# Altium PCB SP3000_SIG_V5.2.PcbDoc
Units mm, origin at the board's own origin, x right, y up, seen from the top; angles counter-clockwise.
Board outline 86.1 x 69.65 mm, 4 copper layers (TopLayer, MidLayer1, GND, BottomLayer); 79 components, 52 nets, 252 pads, 100 vias.
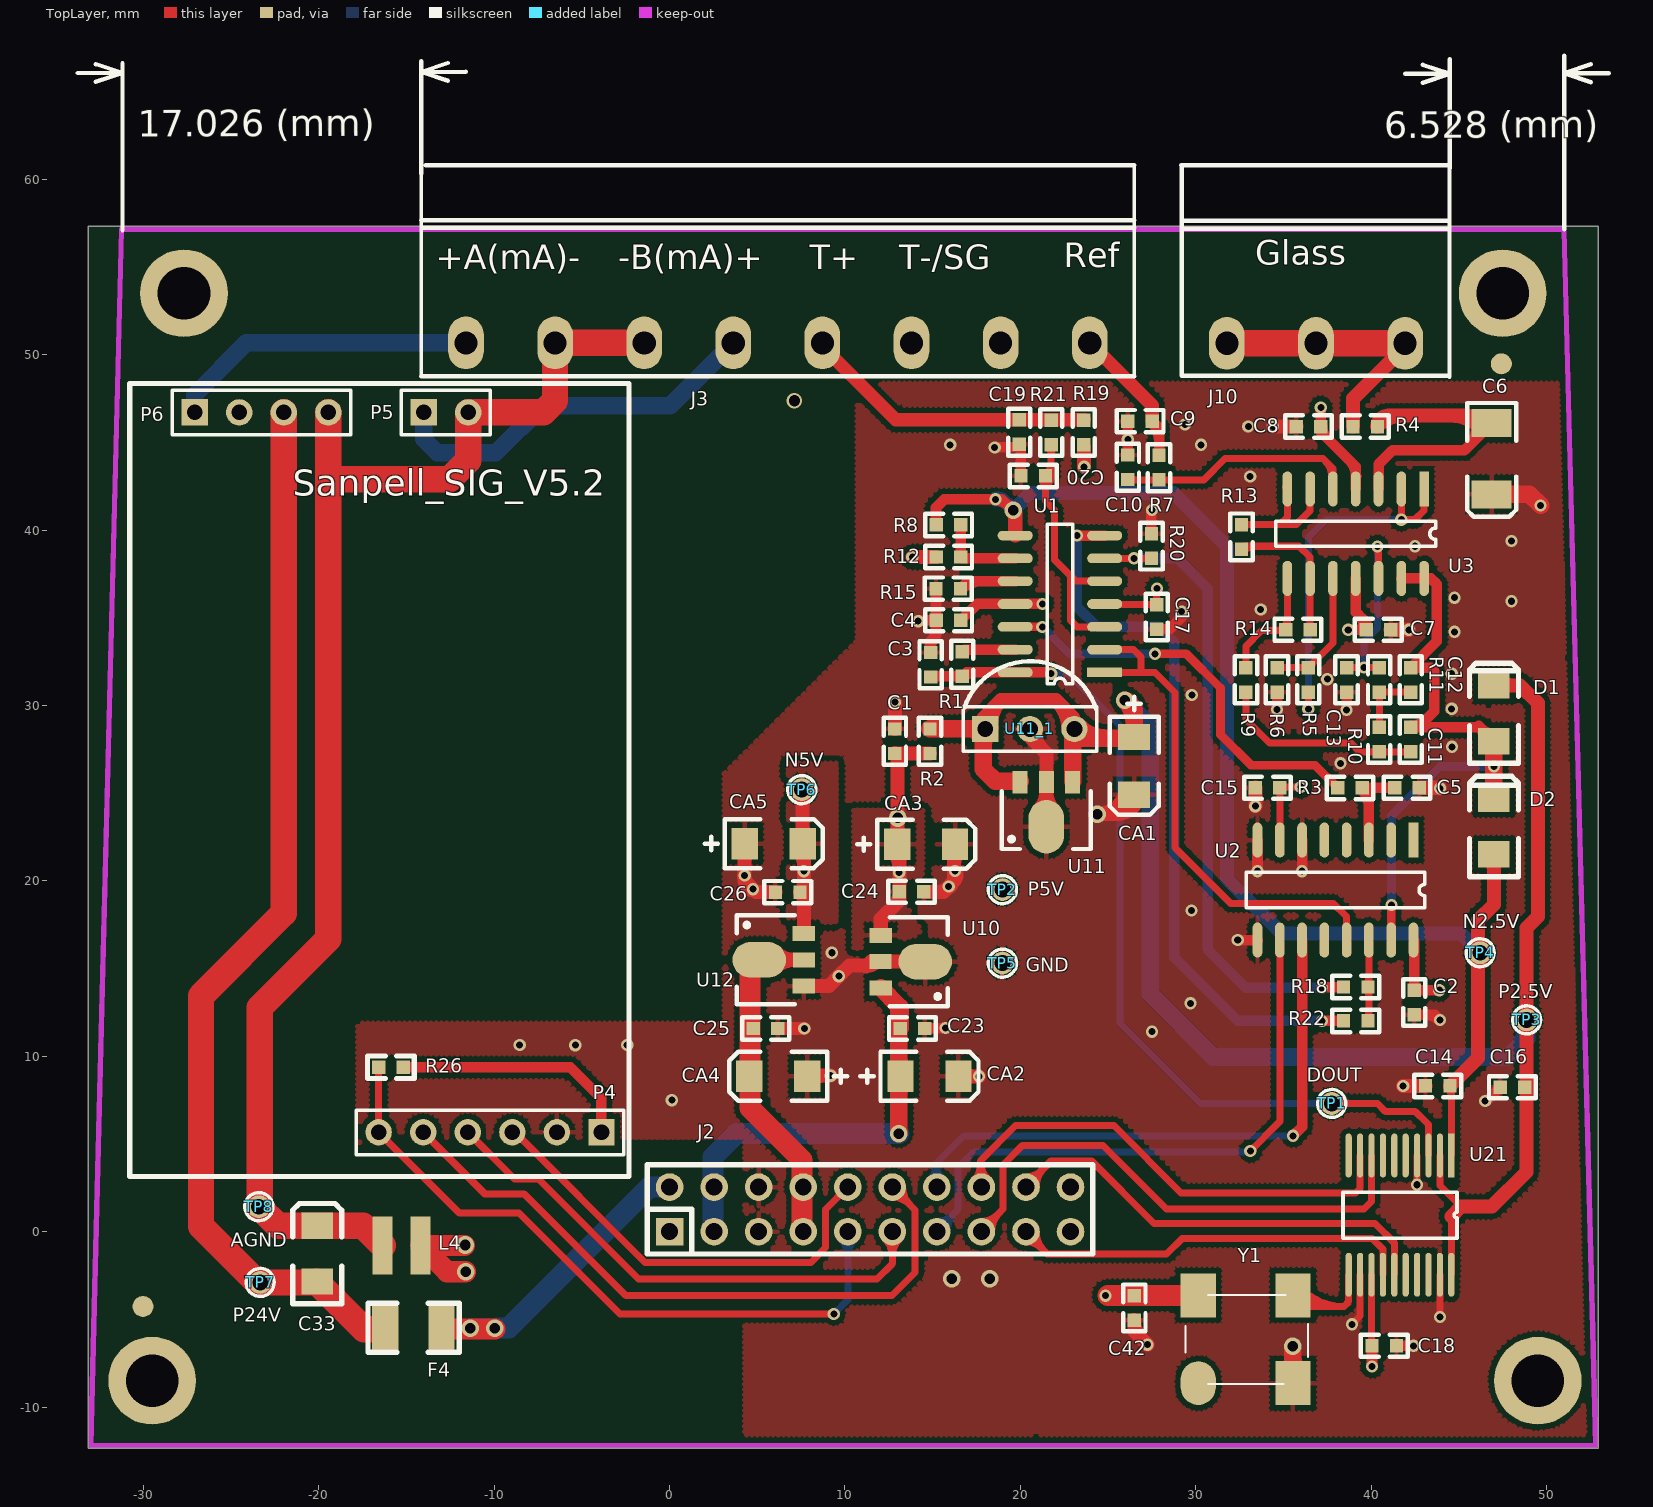
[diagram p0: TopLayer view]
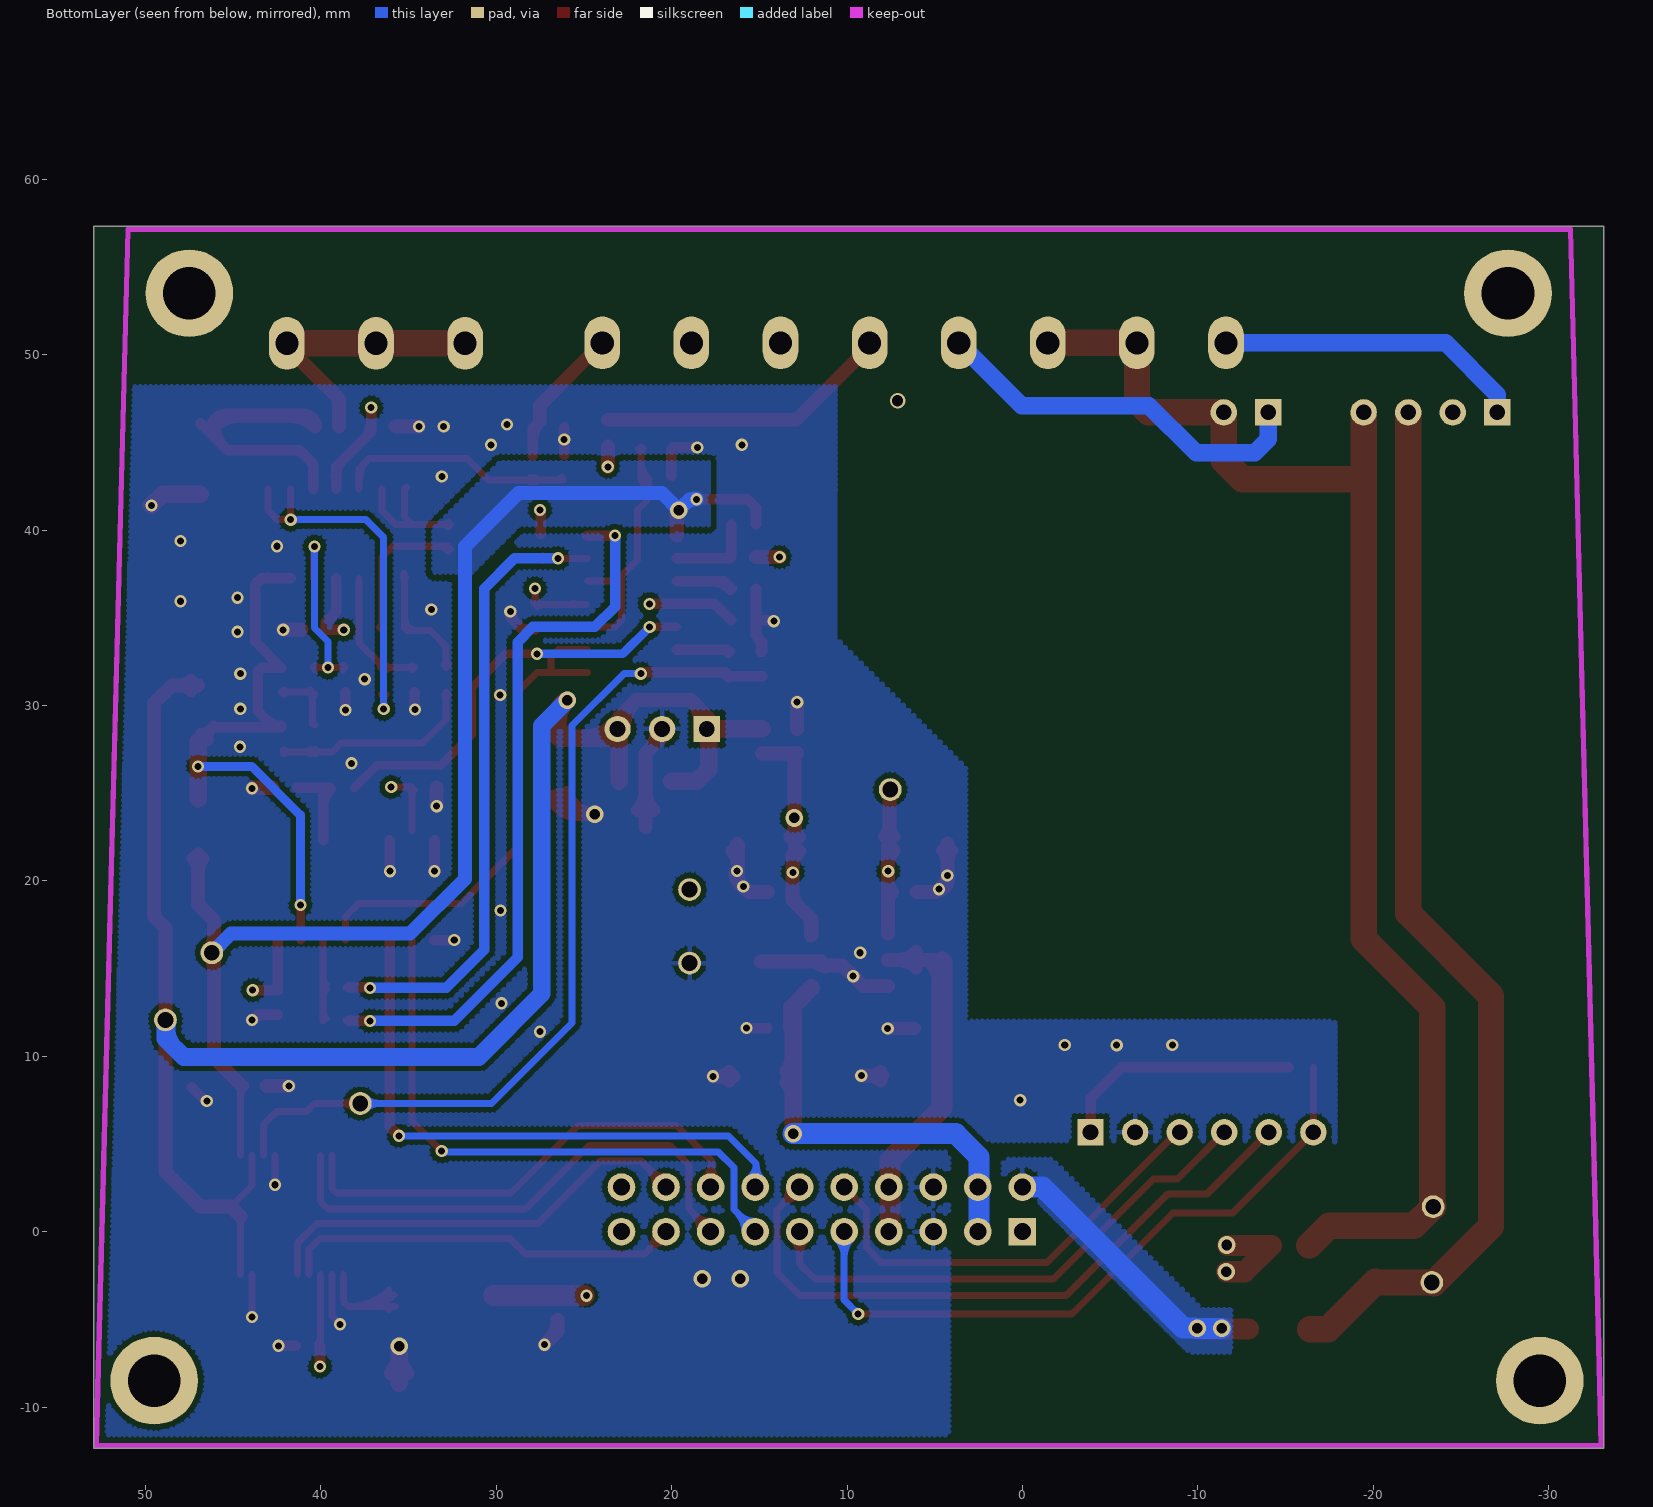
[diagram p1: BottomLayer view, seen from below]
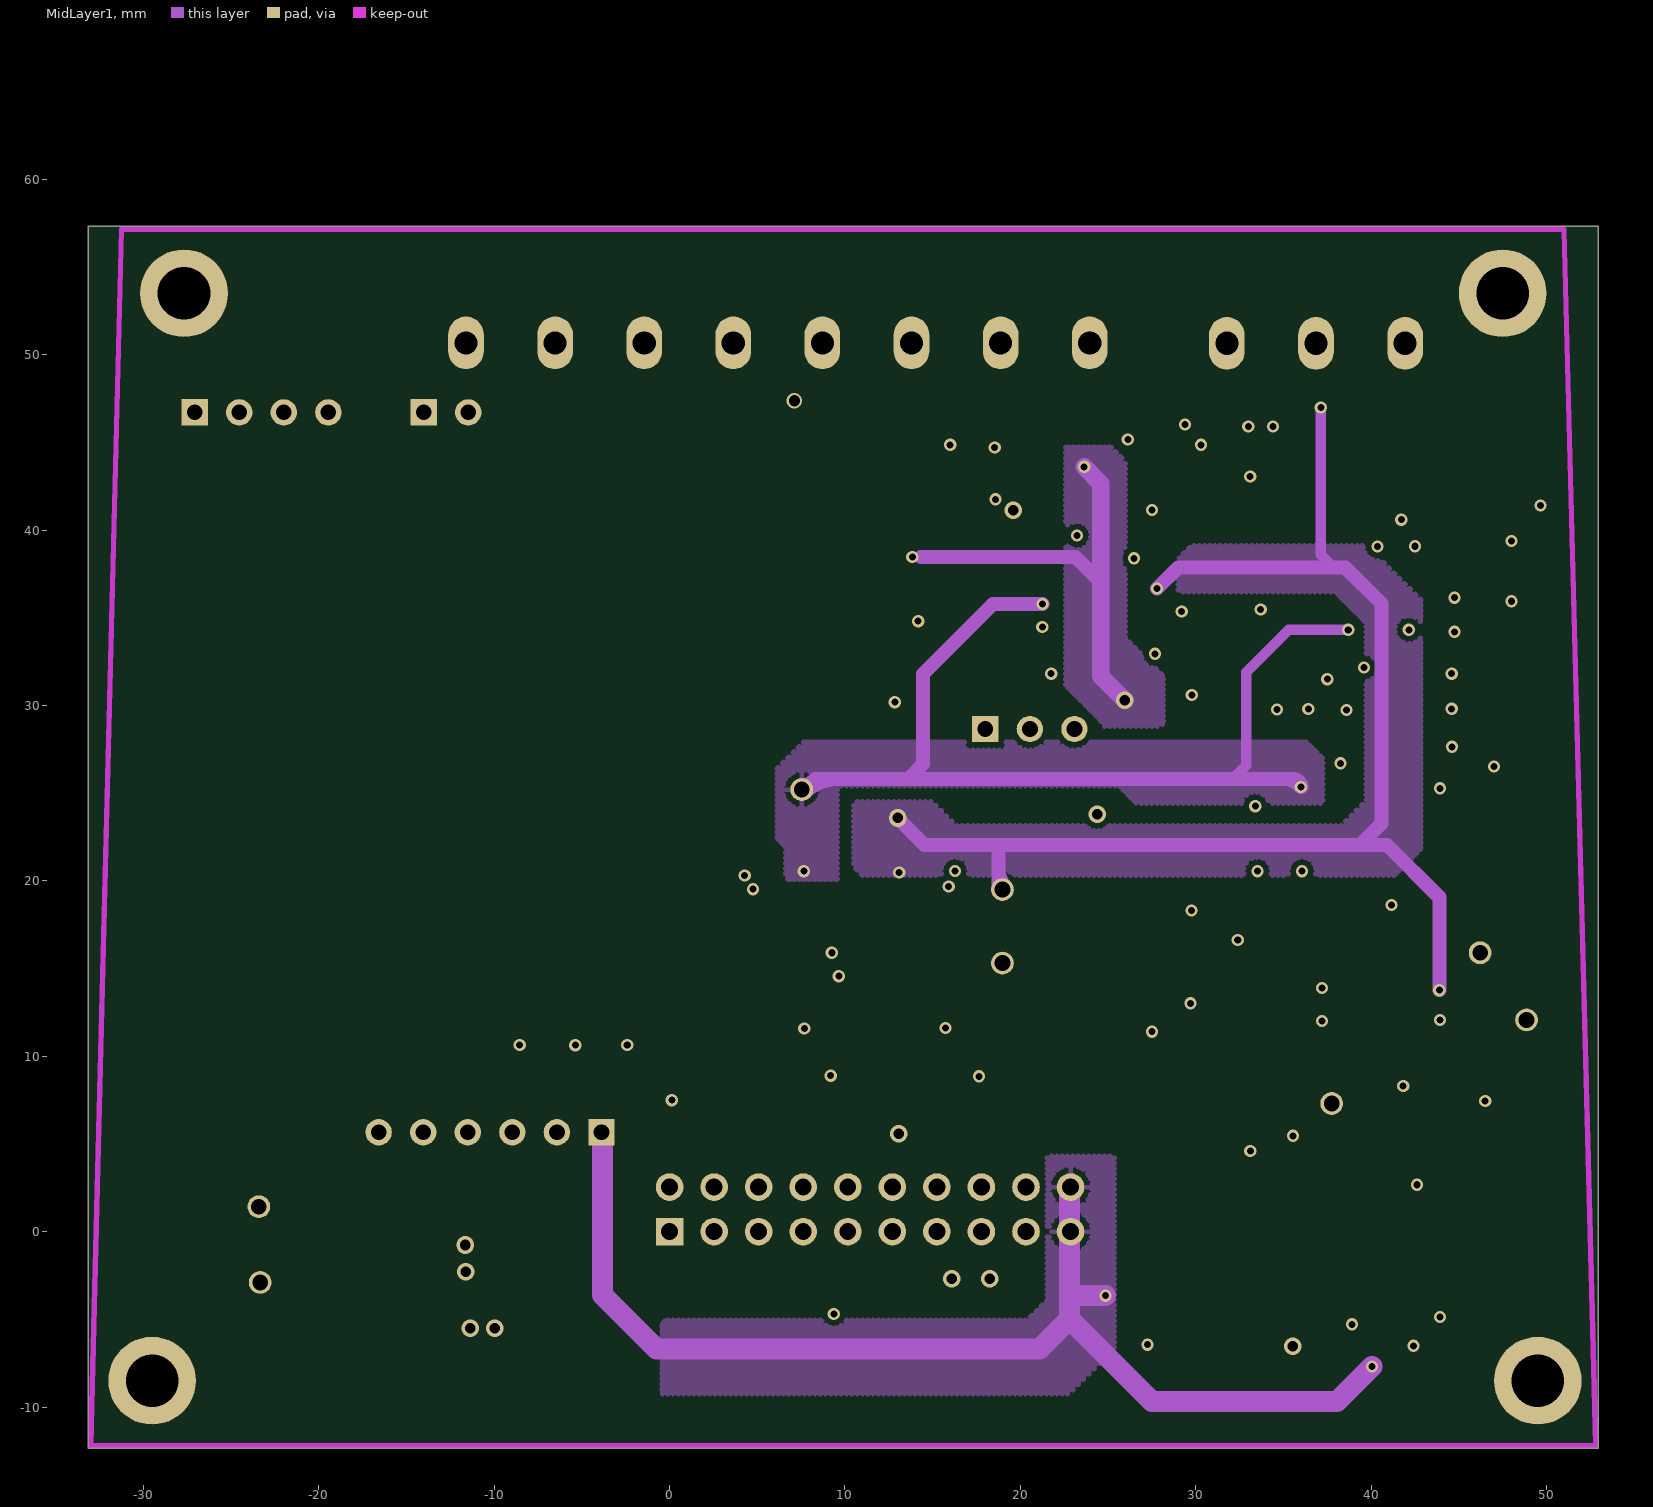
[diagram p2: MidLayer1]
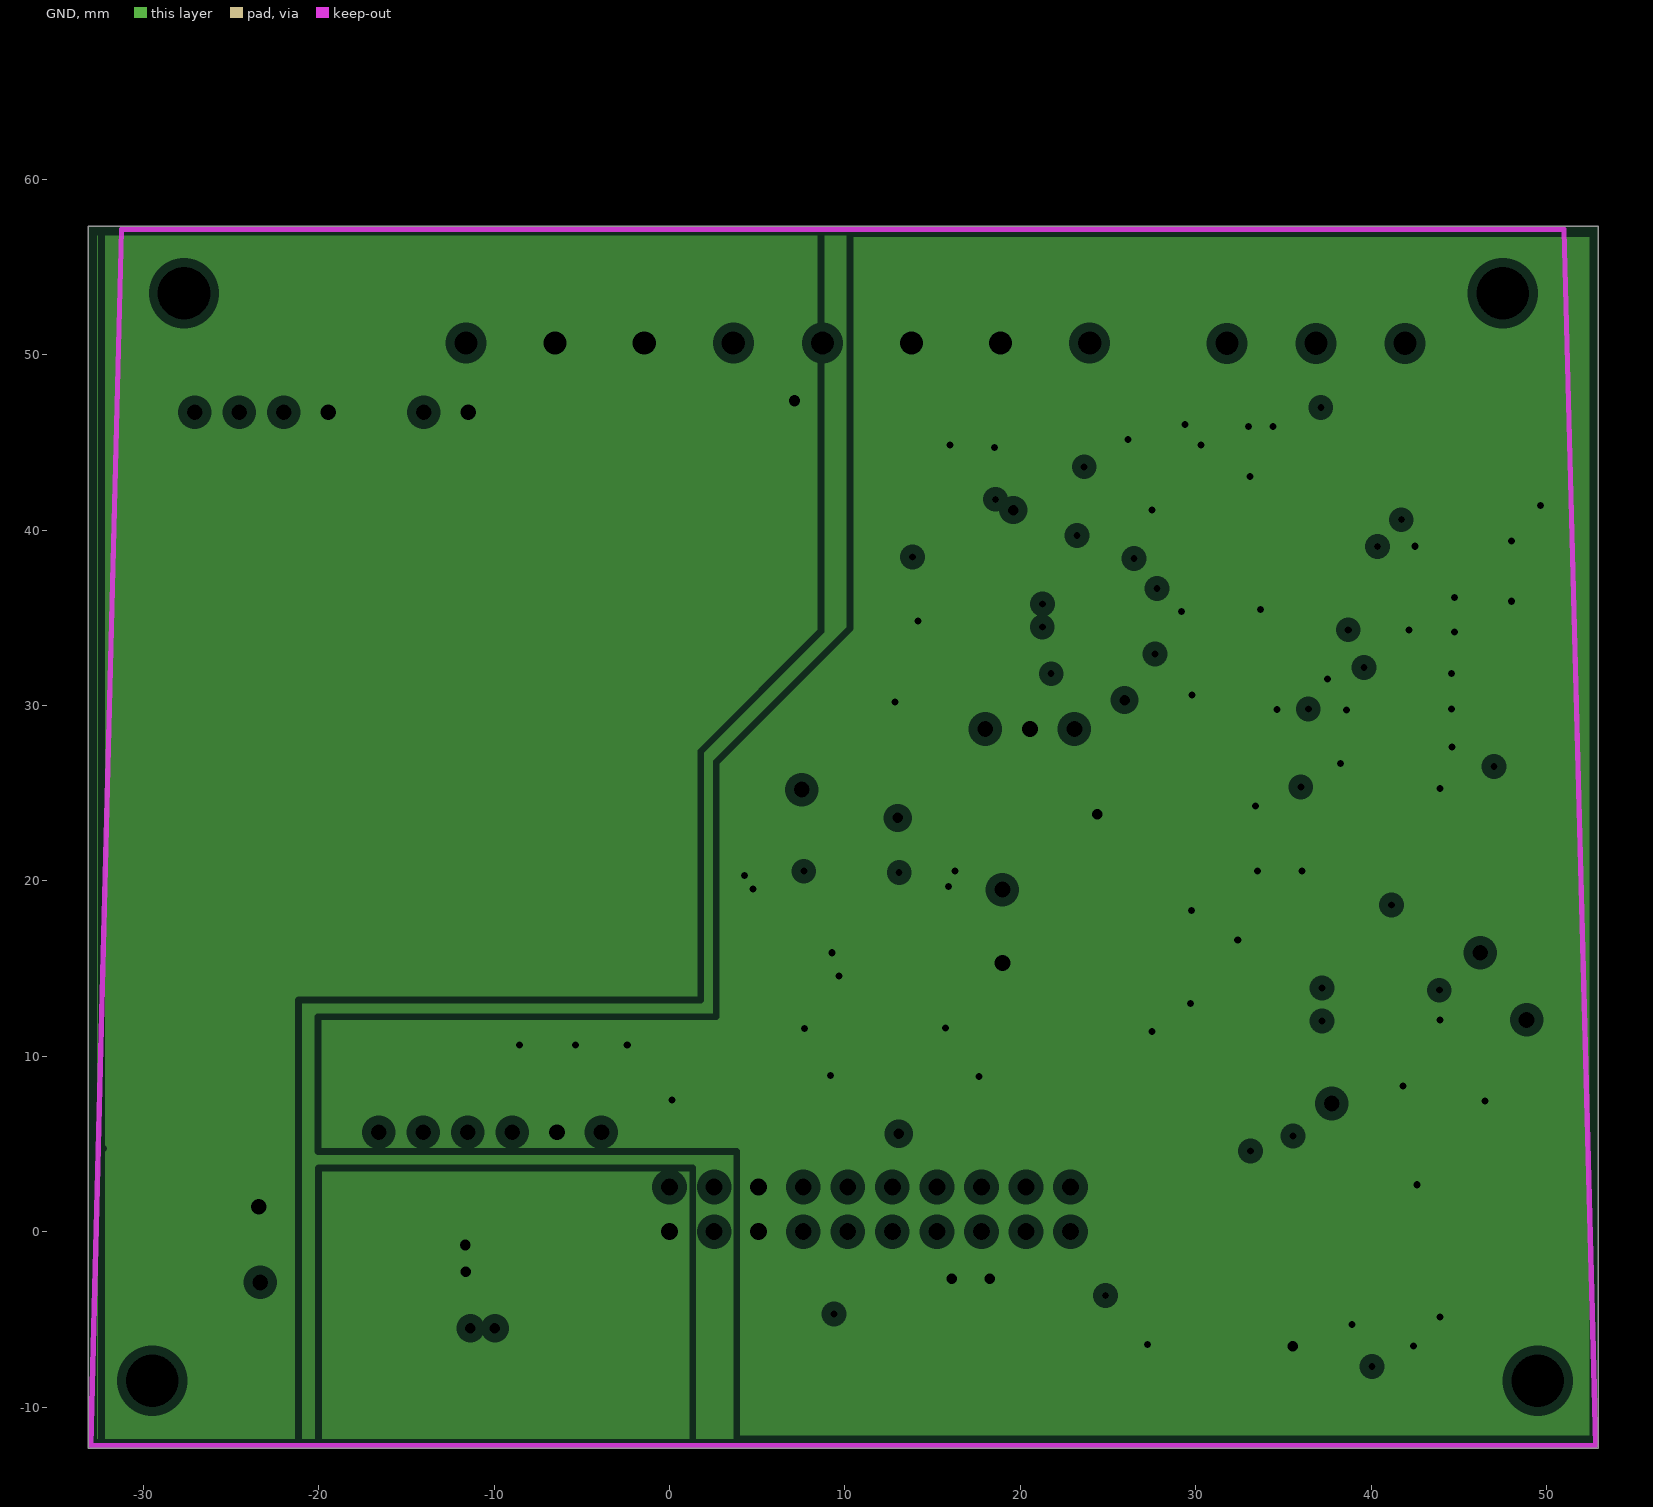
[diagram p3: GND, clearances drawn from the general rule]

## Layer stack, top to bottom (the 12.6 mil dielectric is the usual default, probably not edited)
TopLayer: signal copper 0.0356
Dielectric: core 0.32, FR-4, Dk 4.8
MidLayer1: signal copper 0.0356
Dielectric: prepreg 0.32, FR-4, Dk 4.8
GND: plane copper 0.0356, net (Multiple Nets)
Dielectric: core 0.32, FR-4, Dk 4.8
BottomLayer: signal copper 0.0356

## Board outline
-33.15,-12.342 52.949,-12.342 52.949,57.311 -33.15,57.311

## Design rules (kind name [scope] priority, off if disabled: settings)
Clearance Clearance_poly [InPolygon] p1: gap=0.3
Clearance [All] p2: gap=0.178
FabricationTestPointUsage TestPointUsage [All] p1: valid=0 allowmultiple=FALSE
FabricationTestpoint Testpoint [All] p1: side=3 testpointundercomponent=TRUE minsize=1.016 maxsize=2.54 preferedsize=1.524 minholesize=0.508 maxholesize=1.016 preferedholesize=0.813 testpointgrid=0.025 allowsidetop=TRUE allowsidebottom=TRUE usegrid=TRUE gridtolerance=0
PlaneClearance [All] p1: clearance=0.508
PlaneConnect [All] p1: planeconnectstyle=Relief reliefexpansion=0.508 reliefentries=4 reliefconductorwidth=0.254 reliefairgap=0.254
PolygonConnect PolygonConnect_via [IsVia] p1: connectstyle=Direct reliefconductorwidth=0.254 reliefentries=4 polygonreliefangle="90 Angle"
PolygonConnect [All] p2: connectstyle=Relief reliefconductorwidth=0.254 reliefentries=4 polygonreliefangle="90 Angle"
RoutingLayers [All] p1: top layer_v5=TRUE mid layer 1_v5=FALSE bottom layer_v5=TRUE
RoutingVias [All] p1: holewidth=0.711 width=1.27 viastyle="Through Hole" minholewidth=0.711 minwidth=1.27 maxholewidth=0.711 maxwidth=1.27
SilkscreenOverComponentPads [All] p1: minsilkscreentomaskgap=0.254
SolderMaskExpansion [All] p1: expansion=0.102
Width [All] p1: maxlimit=1.524 minlimit=0.254 preferedwidth=0.8
22 further rules are at their usual default settings.

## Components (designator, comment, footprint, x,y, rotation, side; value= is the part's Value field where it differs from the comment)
C1 "104" 0603 12.844,27.262 r90 top
C2 "104" 0603 42.46,12.37 r90 top
C3 "104" 0603 14.884,33.02 r270 top
C4 "104" 0603 16.606,34.857 r180 top
C5 "104" 0603 41.348,25.308 r0 top
C6 "1uF/50V" 1808C 46.863,45.974 r270 top
C7 "104" 0603 39.71,34.315 r0 top
C8 "104" 0603 37.127,45.898 r180 top
C9 "104" 0603 26.129,46.211 r0 top
C10 "104" 0603 26.129,44.28 r270 top
C11 "104" 0603 42.258,27.356 r90 top
C12 "104" 0603 42.258,32.158 r270 top
C13 "104" 0603 38.6,32.158 r270 top
C14 "104" 0603 44.495,8.308 r180 top
C15 "104" 0603 33.393,25.308 r0 top
C16 "104" 0603 48.75,8.229 r180 top
C17 "104" 0603 27.772,35.746 r270 top
C18 "104" 0603 40.048,-6.509 r0 top
C19 "104" 0603 19.939,44.882 r90 top
C20 "104" 0603 20.033,43.086 r0 top
C23 "104" 0603 14.543,11.583 r180 top
C24 "104" 0603 14.493,19.374 r180 top
C25 "104" 0603 4.78,11.583 r0 top
C26 "104" 0603 6.035,19.356 r0 top
C33 "4.7uF/50V" 1206 -20.091,0.203 r90 top
C42 "104" 0603 26.5,-3.649 r270 top
CA1 "47uF/16V" 1206C 26.48,28.202 r270 top
CA2 "47uF/25V" 1206C 13.168,8.858 r0 top
CA3 "47uF/25V" 1206C 12.974,22.092 r0 top
CA4 "47uF/25V" 1206C 7.844,8.858 r180 top
CA5 "47uF/25V" 1206C 4.285,22.124 r0 top
D1 "IN4148" 1206 47,31.015 r90 top
D2 "IN4148" 1206 47,24.558 r90 top
F4 "6.8uH" 1210 -13.005,-5.486 r180 top
J2 "HEADER 10X2" IDC20 0,0 r0 top locked
J3 "Header 8" W2318R5MIL 23.952,50.673 r0 top
J10 "Header 3" W2313R5MIL 41.935,50.648 r0 top
L4 "6.8uH" LPS3010 -14.199,-0.787 r180 top
P4 "Header 6" HDR1X6 -3.886,5.664 r180 top
P5 "Header 2" HDR1X2 -14.021,46.711 r0 top
P6 "Header 4" HDR1X4 -27.076,46.711 r0 top
R1 "10K" 0603 16.685,31.656 r90 top
R2 "330" 0603 14.844,28.659 r270 top
R3 "100K" 0603 38.092,25.298 r0 top
R4 "10M" 0603 38.963,45.898 r0 top
R5 "10K" 0603 36.416,30.761 r90 top
R6 "10K" 0603 34.638,32.158 r270 top
R7 "10K" 0603 27.907,44.255 r270 top
R8 "10K" 0603 16.606,40.292 r180 top
R9 "150K" 0603 32.86,32.158 r270 top
R10 "150K" 0603 40.454,27.356 r90 top
R11 "150K" 0603 40.454,30.761 r90 top
R12 "10K" 0603 15.209,38.464 r0 top
R13 "10K" 0603 32.606,40.31 r270 top
R14 "10K" 0603 36.52,34.315 r180 top
R15 "10K" 0603 16.586,36.66 r180 top
R18 "10K" 0603 39.819,13.945 r180 top
R19 "10K" 0603 23.614,44.865 r90 top
R20 "10K" 0603 27.474,38.385 r90 top
R21 "10K" 0603 21.76,44.865 r90 top
R22 "10K" 0603 39.819,12.014 r180 top
R26 "47K" 0603A -16.586,9.373 r0 top
TP1 "DOUT" "test point" 37.75,7.308 r0 top
TP2 "P5V" "test point" 18.976,19.501 r0 top
TP3 "P2.5V" "test point" 48.862,12.071 r90 top
TP4 "N2.5V" "test point" 46.214,15.901 r90 top
TP5 "GND" "test point" 18.976,15.308 r0 top
TP6 "N5V" "test point" 7.535,25.201 r0 top
TP7 "P24V" "test point" -23.343,-2.896 r0 top
TP8 "AGND" "test point" -23.419,1.422 r0 top
U1 "LM324" SOP14 24.808,31.885 r180 top
U2 "HC4051" SOP16MAX232 42.41,22.327 r270 top
U3 "LF444" SOP14 43.02,42.342 r270 top
U10 "7805" "7805 - DUPLICATE" 14.392,15.343 r180 top
U11 "TL431" "7805 - DUPLICATE" 21.43,23.272 r90 top
U11_1 "TL431" HDR1X3 18.001,28.659 r0 top
U12 "7905" "7805 - DUPLICATE" 5.299,15.546 r0 top
U21 "CS5529" CS5529 44.569,4.343 r270 top
Y1 "32.768k" CYU-SMD 30.142,-8.636 r90 top

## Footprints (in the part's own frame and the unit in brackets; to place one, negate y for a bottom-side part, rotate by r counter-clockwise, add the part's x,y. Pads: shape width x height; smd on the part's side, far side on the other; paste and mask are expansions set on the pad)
0603 [mil]
  rect 30x30 smd: 1(0,0) 2(55,0)
  silkscreen extent -25,-25 80,25
0603A [mil]
  rect 30x30 smd: 1(0,0) 2(55,0)
  silkscreen extent -25,-25 80,25
1206 [mm]
  rect 1.5x1.8 smd: 1(-3.048,0) 2(0.127,0)
  silkscreen extent -4.32,-1.4 1.4,1.4
1206C [mm]
  rect 1.5x1.8 smd: 1(0,0) 2(3.302,0)
  silkscreen extent -2.29,-1.4 4.44,1.4
1210 [mm]
  rect 1.5x2.5 smd: 1(0,0) 2(3.2,0)
  silkscreen extent -1.02,-1.4 4.19,1.4
1808C [mm]
  rect 1.6x2.3 smd: 1(-0.127,0) 2(3.937,0)
  silkscreen extent -1.27,-1.4 5.21,1.4
"7805 - DUPLICATE" [mil]
  rect 50x34 smd: 1(92.64,57.09) 2(93,-2) 3(92.64,-60.91)
  oval 120x80 smd: 4(-7.36,-1.91)
  silkscreen extent -57,-102 73,98
CS5529 [mm]
  rect 2.5x0.35 smd: 1(0,0)
  oval 2.5x0.35 smd: 2(0,-0.65) 3(0,-1.3) 4(0,-1.95) 5(0,-2.6) 6(0,-3.25) 7(0,-3.9) 8(0,-4.55) 9(0,-5.2) 10(0,-5.85) 11(6.8,-5.85) 12(6.8,-5.2) 13(6.8,-4.55) 14(6.8,-3.9) 15(6.8,-3.25) 16(6.8,-2.6) 17(6.8,-1.95) 18(6.8,-1.3) 19(6.8,-0.65) 20(6.8,0)
  silkscreen extent 2.09,-6.18 4.72,0.32
CYU-SMD [mm]
  oval 2.5x2 smd: 1(0,0)
  rect 2.5x2 smd: 2(0,-5.4) 3(5,-5.4) 4(5,0)
  silkscreen extent -0.05,-6.25 5.03,0.73
HDR1X2 [mm] "Connector; Header; 2 Position"
  rect 1.5x1.5 hole 0.9: 1(0,0)
  round 1.5 hole 0.9: 2(2.54,0)
  silkscreen extent -1.27,-1.27 3.81,1.27
HDR1X3 [mm]
  rect 1.5x1.5 hole 0.9: 1(0,0)
  round 1.5 hole 0.9: 2(2.54,0) 3(5.08,0)
  silkscreen extent -1.27,-1.27 6.35,1.27
HDR1X4 [mm] "Connector; Header; 4 Position"
  rect 1.5x1.5 hole 0.9: 1(0,0)
  round 1.5 hole 0.9: 2(2.54,0) 3(5.08,0) 4(7.62,0)
  silkscreen extent -1.27,-1.27 8.89,1.27
HDR1X6 [mm] "Connector; Header; 6 Position"
  rect 1.5x1.5 hole 0.9: 1(0,0)
  round 1.5 hole 0.9: 2(2.54,0) 3(5.08,0) 4(7.62,0) 5(10.16,0) 6(12.7,0)
  silkscreen extent -1.27,-1.27 13.97,1.27
IDC20 [mil]
  rect 62x62 hole 38: 1(0,0)
  round 62 hole 38: 2(0,100) 3(100,0) 4(100,100) 5(200,0) 6(200,100) 7(300,0) 8(300,100) 9(400,0) 10(400,100) 11(500,0) 12(500,100) 13(600,0) 14(600,100) 15(700,0) 16(700,100) 17(800,0) 18(800,100) 19(900,0) 20(900,100)
  silkscreen extent -50,-50 950,150
LPS3010 [mm]
  rect 1.14x3.3 smd: 1(0,0) 2(2.16,0)
SOP14 [mm]
  rect 2x0.55 smd: 1(0,0)
  oval 2x0.55 smd: 2(0,-1.3) 3(0,-2.6) 4(0,-3.9) 5(0,-5.2) 6(0,-6.5) 7(0,-7.8) 8(5.1,-7.8) 9(5.1,-6.5) 10(5.1,-5.2) 11(5.1,-3.9) 12(5.1,-2.6) 13(5.1,-1.3) 14(5.1,0)
  silkscreen extent 1.84,-8.45 3.27,0.65
SOP16MAX232 [mm]
  rect 2x0.55 smd: 1(0,0)
  oval 2x0.55 smd: 2(0,-1.27) 3(0,-2.54) 4(0,-3.81) 5(0,-5.08) 6(0,-6.35) 7(0,-7.62) 8(0,-8.89) 9(5.7,-8.89) 10(5.7,-7.62) 11(5.7,-6.35) 12(5.7,-5.08) 13(5.7,-3.81) 14(5.7,-2.54) 15(5.7,-1.27) 16(5.7,0)
  silkscreen extent 1.84,-9.53 3.87,0.64
"test point" [mm]
  round 1.3 hole 0.9: 1(0,0)
  silkscreen extent -0.8,-0.8 0.8,0.8
W2313R5MIL [mil]
  oval 80x118.11 hole 52: 1(0,0) 2(-200,0) 3(-400,0)
  silkscreen extent -502,-75 100,400
W2318R5MIL [mil]
  oval 80x118.11 hole 52: 1(0,0) 2(-200,0) 3(-400,0) 4(-600,0) 5(-800,0) 6(-1000,0) 7(-1200,0) 8(-1400,0)
  silkscreen extent -1500,-76 100,400

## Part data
C1 C2 C3 C4 C5 C7 C8 C9 C10 C11 C12 C13 C14 C15 C16 C17 C18 C19 C20 C23 C24 C25 C26 C42: library part Cap, "C?"
C6 CA1 CA2 CA3 CA4 CA5: library part ?, "C"
C33: library part CAP, "Capacitor"
D1 D2: library part ?, "DIODE"
F4 L4: library part INDUCTOR
J3: "Header, 8-Pin"
J10: "Header, 3-Pin"
P4: "Header, 6-Pin"
P5: "Header, 2-Pin"
P6: "Header, 4-Pin"
R1 R2 R3 R4 R5 R6 R7 R8 R9 R10 R11 R12 R13 R14 R15 R18 R19 R20 R21 R22: library part Res, "R?"
R26: library part RES, "电?"
TP1 TP2 TP3 TP4 TP5 TP6 TP7 TP8: library part PAD
U10: library part COMPONENT_4
U11: library part CON4, "Connector"
U11_1: library part "Header 3", "Header, 3-Pin"
Y1: library part "HEADER 2X2"

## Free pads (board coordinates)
  round 5 hole 3: 1(-27.686,53.5) 2(47.5,53.5) 3(49.5,-8.5) 4(-29.5,-8.5)
  round 1.2 smd: MARK1(47.422,49.479) MARK3(-30.023,-4.267)

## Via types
v1: diameter 0.7, hole 0.4, TopLayer to BottomLayer, 87 vias
v2: diameter 1, hole 0.6, TopLayer to BottomLayer, 12 vias
v3: diameter 0.889, hole 0.635, TopLayer to BottomLayer, 1 vias

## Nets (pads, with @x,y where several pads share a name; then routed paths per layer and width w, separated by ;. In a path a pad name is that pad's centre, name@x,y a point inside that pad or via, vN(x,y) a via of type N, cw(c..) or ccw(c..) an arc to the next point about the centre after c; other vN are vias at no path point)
24VGND: J2.1 L4.1 | length 5.7
  TopLayer w1.2: v2@-11.684,-0.787 L4.1 -12.7,-2.286 v2(-11.633,-2.286)
  other v2: -11.659,-0.762
+2.5V: C16.1 CA1.1 D1.2 R2.1 R12.1 R19.1 TP3.1 U11.1 U11.3 U11_1.1 U11_1.3 U21.2 U21.20 | length 148.3
  TopLayer w0.4: U21.2 43.919,2.626 45.123,1.422 ; U21.20 44.569,0.869
  TopLayer w0.8: v1(13.843,38.464) R12.1@15.189,38.464 ; U11_1.1@17.893,28.102 17.893,29.297 18.904,30.308 ; U11_1.1@18.349,28.701 cw(c20.28,28.933) 18.904,30.308 ; 22.068,30.26 cw(c20.467,28.659) U11_1.3@22.731,28.659 ; U11_1.3@23.004,28.133 23.004,29.324 22.02,30.308 18.904,30.308 ; v1(23.64,43.606) R19.1@23.64,44.763 ; 44.569,0.869 45.123,1.422 ; 45.204,1.422 46.874,1.422 48.862,3.41 48.862,17.318 49.5,17.956 49.5,30.138 48.496,31.142 D1.2 ; D1.2@47.397,30.894 cw(c47.995,30.297) 47.995,31.142 cw(c47.995,31.987) D1.2@47.397,31.389
  TopLayer w1: R2.1 17.336,28.659 U11_1.1@17.893,28.102 ; 17.893,27.795 cw(c18.865,27.795) U11_1.1@18.178,28.482 ; U11_1.1@17.924,28.133 U11_1.1@17.893,28.102 ; U11.1@19.98,25.675 18.583,25.675 17.893,26.365 U11_1.1@17.893,28.102 ; U11.3@22.977,25.675 22.977,28.106 23.004,28.133 26.412,28.133 CA1.1 26.48,29.768 v2(25.94,30.308) ; 22.977,27.804 cw(c23.936,27.804) U11_1.3@23.258,28.482 ; U11_1.3@23.258,28.836 ccw(c24.954,30.532) 24.954,28.133 ; 25.561,28.133 ccw(c25.561,28.971) CA1.1@26.154,28.379 ; 26.48,29.004 ccw(c24.636,29.004) v2(25.94,30.308) ; 26.48,29.544 ccw(c25.67,29.544) v2(25.94,30.308)
  MidLayer1 w0.8: 14.343,38.464 23.132,38.464 24.594,37.002
  MidLayer1 w1: v1(23.64,43.606) 24.594,42.651 24.594,37.002 24.594,31.654 v2(25.94,30.308)
  BottomLayer w1: v2(25.94,30.308) 27.398,28.85 27.398,13.553 30.994,9.957 47.817,9.957 48.862,11.002 ; 48.351,10.491 ccw(c47.285,11.558) TP3.1@48.719,12.024 ; 48.862,11.074 TP3.1@48.862,12.014
+5V: C1.1 C2.2 C8.1 C17.1 C24.2 CA3.1 R2.2 TP2.1 U1.4 U2.16 U3.4 U10.3 | length 112.6
  TopLayer w0.4: U1.4@24.847,35.746 C17.1 27.772,36.643 v1(27.793,36.664) ; U1.4@25.586,35.838 ccw(c25.809,36.061) 25.809,35.746 ; C17.1@27.644,35.618 ccw(c27.335,35.309) 27.335,35.746 ccw(c27.335,36.183) 27.644,35.874 ccw(c27.335,36.183) 27.772,36.183 ccw(c28.209,36.183) C17.1@27.9,35.874 ; 27.772,36.25 cw(c28.207,36.25) v1@27.899,36.558
  TopLayer w0.6: v1(37.127,46.987) C8.1 37.127,45.6 39.12,43.607 U3.4 ; C8.1@37.208,45.898 ccw(c38.121,45.898) 37.475,45.252 ; 38.78,43.947 cw(c37.901,43.067) U3.4@39.145,43.067 ; U2.16@42.46,16.576 C2.2 v1(43.883,13.767)
  TopLayer w0.8: U10.3 12.039,17.816 13.096,18.874 C24.2 13.096,21.469 12.974,21.592 CA3.1 13.006,22.124 v2(13.006,23.584) C1.1@13.006,27.203 ; CA3.1@12.726,21.694 cw(c11.833,20.801) v1@13.096,20.801 ; CA3.1@12.726,22.489 ccw(c12.051,23.165) v2@13.006,23.165 ; 12.775,18.553 ccw(c11.954,19.374) C24.2@13.115,19.374 ; C1.1@12.857,27.276 cw(c12.498,26.916) C1.1@13.006,26.916 ; C1.1@12.918,27.262 R2.2 ; 13.006,23.008 ccw(c13.74,23.008) CA3.1@13.221,22.489
  MidLayer1 w0.6: v1(37.127,46.987) 37.127,38.589 37.844,37.871
  MidLayer1 w0.8: v2(13.006,23.584) 14.543,22.047 39.369,22.047 ; 18.75,20.65 ccw(c20.125,20.65) TP2.1@19.153,19.677 ; 18.75,21.469 18.75,19.727 TP2.1 ; v1(27.793,36.664) 29.001,37.871 37.844,37.871 38.524,37.871 40.594,35.802 40.594,23.272 39.369,22.047 ; v1(43.883,13.767) 43.883,19.065 40.901,22.047 39.369,22.047
  other v1: 13.093,20.473
+12V: C23.2 CA2.1 J2.3 J2.4 U10.1 | length 26.9
  TopLayer w1: U10.1 13.07,12.862 ; v2(13.07,5.588) 13.07,12.862 ; 13.07,7.867 cw(c14.009,7.867) CA2.1@13.345,8.531 ; 13.07,9.849 ccw(c14.009,9.849) CA2.1@13.345,9.185 ; C23.2 13.146,12.785 13.07,12.862
  BottomLayer w1.2: J2.3@2.481,0 2.481,2.54 2.481,4.267 3.802,5.588 v2(13.07,5.588)
+24V: C33.1 F4.2 P6.3 TP7.1 | length 61
  TopLayer w1.5: TP7.1@-23.47,-2.946 -26.721,0.305 -26.721,13.437 -21.996,18.161 P6.3 ; TP7.1 -20.193,-2.896 -20.142,-2.845 -17.424,-5.563 F4.2@-16.409,-5.563
+24V_IN: F4.1 J2.2 | length 17.6
  TopLayer w1.2: F4.1@-12.878,-5.563 v2@-9.957,-5.563
  BottomLayer w1.2: v2(-11.354,-5.512) -9.855,-5.512 -9.83,-5.486 -9.169,-5.486 -1.143,2.54 J2.2
  other v2: -9.957,-5.512
-2.5V: C14.1 D2.1 R8.2 TP4.1 U1.8 U21.1 | length 83.5
  TopLayer w0.4: C14.1@44.367,8.18 cw(c43.877,7.691) 44.569,7.691 ; C14.1@44.492,8.306 44.569,8.229 U21.1
  TopLayer w0.6: R8.2@15.189,40.318 15.189,41.269 15.672,41.752 v1(18.583,41.752) 18.929,41.752 v2@19.708,40.973 ; v1@18.583,41.702 cw(c18.583,40.746) v2@19.259,41.422 ; 19.158,41.523 ccw(c19.594,41.958) v2@19.594,41.342
  TopLayer w0.8: v2@19.523,41.071 cw(c19.077,40.625) 19.708,40.625 ; U1.8 v2@19.708,40.973 ; C14.1@44.492,8.306 C14.1 46.094,9.907 46.094,17.752 47,18.658 D2.1 ; 46.094,15.007 cw(c47.108,15.007) TP4.1@46.391,15.724 ; 46.094,16.794 ccw(c47.108,16.794) TP4.1@46.391,16.078 ; D2.1@46.753,21.263 cw(c46.155,20.665) 47,20.665 cw(c47.845,20.665) D2.1@47.247,21.263
  BottomLayer w0.8: v1(18.583,41.752) 18.984,41.752 v2(19.594,41.142) 20.56,42.108 28.738,42.108 31.793,39.053 31.793,20.117 34.913,16.996 45.118,16.996 TP4.1 ; v1(18.583,41.752) cw(c18.583,40.777) v2@19.5,41.108 ; v1@18.583,41.802 cw(c18.583,40.954) 19.182,41.554 ccw(c18.583,40.954) v1@18.583,41.802
-5V: C4.1 C7.1 C15.2 C26.2 CA5.2 TP6.1 U1.11 U2.7 U3.11 U12.1 | length 89.5
  TopLayer w0.4: C15.2@34.662,25.18 cw(c34.353,24.871) 34.79,24.871 cw(c35.227,24.871) 34.918,25.18 cw(c35.327,24.772) 35.327,25.349 ; U2.7@34.79,22.835 C15.2 34.79,25.349 v1@35.908,25.349 ; v1@35.881,25.243 ccw(c35.625,24.987) 35.625,25.349 ccw(c35.625,25.711) v1@35.881,25.455
  TopLayer w0.6: CA5.2@7.506,22.074 CA5.2@7.652,21.929 ; C4.1 17.534,35.785 U1.11 v1(21.256,35.785) ; v1(38.694,34.315) C7.1 ; U3.11 39.12,35.32 39.71,34.73 C7.1 ; 39.278,35.162 cw(c38.431,34.315) C7.1@39.629,34.315 ; C7.1@39.62,34.405 C7.1
  TopLayer w0.8: CA5.2@7.339,21.726 cw(c6.586,20.973) 7.652,20.973 ; CA5.2@7.339,22.521 ccw(c6.742,23.119) 7.587,23.119 ccw(c8.432,23.119) CA5.2@7.834,22.521 ; TP6.1@7.358,25.024 cw(c6.807,24.472) 7.587,24.472 ; C26.2@7.446,19.343 ccw(c6.948,19.84) 7.652,19.84 ; C26.2@7.446,19.37 cw(c6.948,18.873) 7.652,18.873 ; TP6.1 7.587,25.149 CA5.2 ; U12.1 v1(7.652,20.55) CA5.2@7.652,21.929
  MidLayer1 w0.6: 32.098,25.808 32.885,26.595 32.885,31.892 35.308,34.315 v1(38.694,34.315)
  MidLayer1 w0.8: TP6.1@7.506,25.021 8.293,25.808 13.61,25.808 ; TP6.1@7.535,25.451 ccw(c7.535,26.418) 8.219,25.734 ; TP6.1@7.712,25.024 cw(c9.605,23.131) 9.605,25.808 ; v1(21.256,35.785) 18.451,35.785 14.458,31.792 14.458,26.656 13.61,25.808 ; 35,25.808 cw(c35,24.362) v1@36.022,25.385 ; v1(35.987,25.349) 35.528,25.808 ; v1@36.036,25.355 ccw(c35.528,25.296) 35.528,25.808 ; 13.61,25.808 32.098,25.808 35.528,25.808
-12V: C25.1 CA4.2 J2.7 J2.8 U12.2 U12.4 | length 22.5
  TopLayer w0.8: U12.4@4.943,15.496 U12.2 ; U12.4@6.055,15.062 cw(c7.101,14.016) U12.2@7.101,15.496 ; U12.4@6.055,15.933 ccw(c7.112,16.991) U12.2@7.112,15.496
  TopLayer w1.2: 4.594,14.47 cw(c5.631,14.47) U12.4@4.898,15.204 ; U12.4@4.594,15.37 4.594,7.045 7.561,4.077 7.561,2.54 J2.7@7.561,0
CS-CS: J2.15 U21.8 | length 32.3
  TopLayer w0.4: J2.15@17.721,0 19.017,1.295 19.017,3.81 20.11,4.903 24.717,4.903 28.325,1.295 39.591,1.295 40.019,1.724 U21.8 ; J2.15@17.78,0.587 ccw(c17.78,1.864) 18.683,0.961 ; J2.15@18.367,0 cw(c19.927,0) 18.824,1.103
CS-SCK: J2.16 U21.9 | length 29.7
  TopLayer w0.4: J2.16@17.365,2.955 ccw(c16.503,3.817) 17.721,3.817 ; J2.16@17.721,2.54 17.721,4.039 ; J2.16@18.183,2.967 cw(c19.195,4.039) 17.721,4.039 ; U21.9 39.369,2.471 39.108,2.21 29.167,2.21 25.331,6.045 19.728,6.045 17.721,4.039
CS-SDI: J2.18 U21.15 | length 27.7
  TopLayer w0.4: J2.18@20.261,2.54 21.76,4.039 24.049,4.039 27.624,0.464 40.219,0.464 41.319,-0.636 U21.15 ; J2.18@20.32,3.127 ccw(c20.32,4.404) 21.223,3.501 ; J2.18@20.907,2.54 cw(c22.467,2.54) 21.364,3.643
CS-SDO: J2.17 U21.14 | length 25.2
  TopLayer w0.4: J2.17@20.261,0 21.531,-1.27 28.339,-1.27 29.228,-0.381 40.048,-0.381 40.669,-1.002 U21.14 ; J2.17@20.32,-0.587 cw(c20.32,-1.864) 21.223,-0.961 ; J2.17@20.907,0 ccw(c22.467,0) 21.364,-1.103
CURA: J3.8 P6.1 | length 17.7
  BottomLayer w1: P6.1 -27.076,47.727 -24.13,50.673 J3.8
CURB: J3.5 P5.1 | length 22.1
  BottomLayer w1: P5.1 -14.021,45.187 -13.233,44.399 -9.906,44.399 -7.214,47.092 0.051,47.092 J3.5
DOUT: C3.2 R1.1 TP1.1 U1.14 U21.3 | length 56.5
  TopLayer w0.4: v1@21.684,31.885 v1(21.76,31.809) ; TP1.1 40.356,7.308 40.806,6.858 42.512,6.858 ; TP1.1@38.068,6.99 cw(c38.836,6.222) 38.836,7.308 cw(c38.836,8.394) TP1.1@38.068,7.626 ; U21.3 43.269,6.101 43.118,6.252 ; 42.512,6.858 43.118,6.252 ; 42.512,6.858 43.118,6.252
  TopLayer w0.6: C3.2@14.834,31.656 R1.1 16.713,31.656 16.942,31.885 U1.14 v1@21.684,31.885 ; R1.1@16.742,31.599 cw(c17.432,30.909) 17.432,31.885
  BottomLayer w0.4: v1(21.76,31.809) 22.719,31.809 25.672,28.856 25.672,11.904 30.268,7.308 TP1.1 ; v1@21.866,31.703 cw(c22.122,31.447) 22.122,31.809 cw(c22.122,32.171) v1@21.866,31.915 ; TP1.1@37.432,6.99 ccw(c36.664,6.222) 36.664,7.308 ccw(c36.664,8.394) TP1.1@37.432,7.626
IAGND: C33.2 J3.6 J3.7 L4.2 P5.2 P6.4 TP8.1 | length 79.7
  TopLayer w1.5: TP8.1 -22.327,0.33 -20.142,0.33 -17.476,0.33 L4.2 ; TP8.1@-23.368,1.422 -23.368,12.776 -19.456,16.688 -19.456,42.901 ; P6.4 -19.456,42.901 ; J3.6 J3.7 -6.528,47.371 -7.188,46.711 P5.2 -11.481,43.967 -12.548,42.901 -19.456,42.901
  other v3: 7.112,47.371
MISO1: J2.10 P4.3 | length 25.3
  TopLayer w0.4: P4.3 -8.814,5.664 -1.397,-1.753 8.052,-1.753 8.89,-0.914 8.89,1.27 J2.10
MOSI1: J2.11 P4.4 | length 32.1
  TopLayer w0.4: P4.4 -8.839,2.997 -7.468,2.997 -1.771,-2.699 11.831,-2.699 12.7,-1.83 J2.11 ; J2.11@12.285,-0.415 cw(c11.282,-1.418) 12.7,-1.418 cw(c14.118,-1.418) J2.11@13.115,-0.415
NetC5_1: C5.1 R3.2 U2.3 | length 6.2
  TopLayer w0.6: R3.2@39.432,25.241 cw(c38.374,24.183) 39.87,24.183 ; U2.3 39.87,24.917 R3.2 41.338,25.298 C5.1
NetC6_1: C6.1 R4.2 U3.3 | length 21.1
  TopLayer w0.6: U3.3 40.42,43.76 41.218,44.558 45.32,44.558 C6.1 ; 45.495,44.733 ccw(c44.238,45.99) C6.1@46.014,46.077
  TopLayer w0.8: R4.2@40.341,45.898 cw(c40.987,45.879) 40.987,46.525 ; R4.2@40.346,45.911 cw(c41.828,44.43) 41.828,46.525 ; R4.2 40.987,46.525 ; 44.524,46.525 cw(c44.524,44.112) C6.1@46.23,45.818 ; C6.1@46.129,45.988 ccw(c45.41,45.775) 45.41,46.525 40.987,46.525
NetC10_2: C10.2 R7.2 U3.5 | length 16.3
  TopLayer w0.4: C10.2@26.154,42.858 R7.2 30.458,42.858 31.669,44.069 37.254,44.069 37.82,43.503 U3.5 ; C10.2@26.257,43.011 ccw(c26.627,43.381) 26.627,42.858 ; R7.2@27.779,42.73 ccw(c27.47,42.421) 27.47,42.858 ccw(c27.47,43.295) R7.2@27.779,42.986 ; R7.2@28.035,42.73 cw(c28.344,42.421) 28.344,42.858 cw(c28.344,43.295) R7.2@28.035,42.986 ; 37.383,43.94 cw(c36.51,43.067) U3.5@37.745,43.067
NetC11_1: C11.1 R9.2 R10.1 | length 14.4
  TopLayer w0.4: R9.2@32.732,30.633 cw(c32.423,30.324) 32.86,30.324 cw(c33.297,30.324) R9.2@32.988,30.633 ; R9.2 32.86,29.21 34.213,27.857 38.844,27.857 39.345,27.356 R10.1 C11.1@42.146,27.356 ; R10.1@40.326,27.228 ccw(c40.017,26.919) 40.017,27.356 ccw(c40.017,27.793) R10.1@40.326,27.484 ; R10.1@40.582,27.228 cw(c40.891,26.919) 40.891,27.356 cw(c40.891,27.793) R10.1@40.582,27.484 ; C11.1@42.13,27.228 ccw(c41.821,26.919) 41.821,27.356 ccw(c41.821,27.793) C11.1@42.13,27.484
NetC11_2: C11.2 C12.1 D1.1 D2.2 U2.15 U3.13 U3.14 | length 38.7
  TopLayer w0.5: U2.15 v1@41.14,18.644
  TopLayer w0.6: U3.13 U3.14 43.409,37.242 43.75,36.901 43.75,33.65 C12.1 43.393,32.158 43.604,31.947 43.604,29.68 42.677,28.753 ; C11.2 42.677,28.753 ; C11.2@42.258,28.834 ccw(c42.258,30.041) 43.111,29.187 ; U3.14@43.018,37.267 cw(c43.069,36.513) 43.603,37.047 ; U3.14@43.02,37.267 cw(c43.02,36.388) 43.641,37.009 ; 46.139,28.828 cw(c45.475,28.164) D1.1@46.405,28.031 ; D1.1@46.338,28.629 ccw(c46.85,29.141) D1.1@46.85,28.417 ; D1.1 46.214,28.753 42.677,28.753
  TopLayer w1: D2.2 v1(47,26.525) D1.1
  BottomLayer w0.5: v1(41.166,18.618) 41.166,23.749 43.942,26.525 v1(47,26.525)
NetC12_2: C12.2 R10.2 R11.1 | length 5.5
  TopLayer w0.4: R10.2@40.326,28.881 ccw(c39.956,29.251) 40.48,29.251 ; R11.1@40.326,30.633 cw(c39.956,30.263) 40.48,30.263 ; R10.2@40.48,28.947 R11.1@40.48,30.598 ; R11.1@40.582,30.633 cw(c40.891,30.324) 40.891,30.761 cw(c40.891,31.198) R11.1@40.582,30.889 ; R11.1@40.607,30.761 C12.2 ; C12.2@42.13,30.633 ccw(c41.821,30.324) 41.821,30.761 ccw(c41.821,31.198) C12.2@42.13,30.889
NetC13_1: C13.1 R11.2 U3.12 | length 15
  TopLayer w0.4: C13.1 v1(39.594,32.158) R11.2 ; C13.1@38.728,32.03 cw(c39.037,31.721) 39.037,32.158 cw(c39.037,32.595) C13.1@38.728,32.286 ; v1@39.488,32.052 ccw(c39.232,31.796) 39.232,32.158 ccw(c39.232,32.52) v1@39.488,32.264 ; v1@39.7,32.052 cw(c39.956,31.796) 39.956,32.158 cw(c39.956,32.52) v1@39.7,32.264 ; v1@40.254,38.955 cw(c39.853,38.554) 40.42,38.554 ; R11.2@40.326,32.03 ccw(c40.017,31.721) 40.017,32.158 ccw(c40.017,32.595) R11.2@40.326,32.286 ; v1(40.36,39.061) 40.42,39.001 U3.12
  BottomLayer w0.4: v1@39.488,32.264 ccw(c39.232,32.52) 39.594,32.52 ccw(c39.956,32.52) v1@39.7,32.264 ; v1(39.594,32.158) 39.594,33.639 40.36,34.405 v1(40.36,39.061) v1@40.344,39.077 ; v1@40.254,38.955 cw(c39.998,38.699) 40.36,38.699 cw(c40.722,38.699) v1@40.466,38.955
NetC20_2: C20.2 R21.1 U1.3 U1.5 | length 17.9
  TopLayer w0.4: 21.302,42.654 cw(c20.993,42.345) 21.43,42.345 cw(c21.867,42.345) 21.558,42.654 ; C20.2@21.302,42.91 ccw(c20.196,44.016) 21.76,44.016 ; 21.585,42.627 ccw(c21.161,43.05) C20.2@21.76,43.05 ; R21.1@21.632,44.635 cw(c21.323,44.326) 21.76,44.326 cw(c22.197,44.326) R21.1@21.888,44.635 ; R21.1@21.76,44.737 21.76,43.112 21.43,42.782 21.43,41.65 21.938,41.142 21.938,38.306 22.852,37.392 ; U1.3 23.224,34.485 22.852,34.857 22.852,37.392 ; U1.5 23.159,37.085 22.852,37.392
NetC33_1: 
NetR1_2: R1.2 U1.13 | length 3.6
  TopLayer w0.6: R1.2 16.816,33.185 U1.13 ; R1.2@16.742,32.996 cw(c17.198,32.54) 17.198,33.185
NetR3_1: R3.1 U1.12 | length 23.7
  TopLayer w0.5: U1.12 21.241,34.485 v1(21.25,34.476) ; v1(27.679,32.943) 29.461,32.943 31.412,30.992 31.412,28.339 33.155,26.595 36.795,26.595 R3.1
  BottomLayer w0.5: v1(21.25,34.476) 22.783,32.943 v1(27.679,32.943)
NetR5_1: R5.1 U3.1 U3.2 | length 24.6
  TopLayer w0.4: R5.1@36.288,30.633 cw(c35.979,30.324) 36.416,30.324 cw(c36.853,30.324) R5.1@36.544,30.633 ; v1@36.31,29.9 ccw(c36.054,30.156) 36.416,30.156 ccw(c36.778,30.156) v1@36.522,29.9 ; v1(36.416,29.794) R5.1 R5.1@36.416,30.888 ; v1@41.614,40.695 ccw(c41.358,40.951) 41.72,40.951 ccw(c42.082,40.951) 41.826,40.695 ccw(c42.082,40.951) 42.082,40.589 ccw(c42.082,40.227) v1@41.826,40.483 ; U3.2 v1(41.72,40.589) 42.486,40.589 43.02,41.123 U3.1
  BottomLayer w0.4: v1@36.31,29.9 ccw(c36.054,30.156) 36.416,30.156 ccw(c36.778,30.156) v1@36.522,29.9 ; v1(36.416,29.794) 36.416,39.573 37.432,40.589 v1(41.72,40.589) ; v1@41.614,40.483 ccw(c41.358,40.227) 41.358,40.589 ccw(c41.358,40.951) v1@41.614,40.695
NetR5_2: R5.2 R6.1 U3.10 | length 9.5
  TopLayer w0.4: R6.1 R5.2 37.82,33.562 U3.10 ; R6.1@34.766,32.03 cw(c35.075,31.721) 35.075,32.158 cw(c35.075,32.595) R6.1@34.766,32.286 ; R5.2@36.288,32.03 ccw(c35.979,31.721) 35.979,32.158 ccw(c35.979,32.595) R5.2@36.288,32.286 ; R5.2@36.416,32.339 ccw(c36.416,32.776) 36.725,32.467 ccw(c37.034,32.158) R5.2@36.597,32.158
NetR8_1: R8.1 R12.2 U1.9 | length 5.3
  TopLayer w0.6: R8.1 R12.2 16.685,38.385 U1.9 ; R12.2@16.663,38.521 ccw(c16.992,38.849) 16.992,38.385
NetR9_1: R9.1 R14.2 U3.8 | length 8.9
  TopLayer w0.4: R9.1@32.732,32.286 ccw(c32.423,32.595) 32.86,32.595 ccw(c33.297,32.595) R9.1@32.988,32.286 ; R9.1 32.86,33.375 33.749,34.264 35.072,34.264 R14.2 35.22,34.412 U3.8 ; 34.563,34.264 ccw(c34.563,34.876) 34.995,34.443 ccw(c34.452,34.987) 35.22,34.987 ; U3.8@35.179,37.338 35.247,37.269 U3.8@35.247,37.516
NetR13_1: R13.1 U3.6 U3.7 | length 8.5
  TopLayer w0.4: R13.1 34.79,40.31 ; R13.1@32.734,40.182 cw(c33.043,39.873) 33.043,40.31 cw(c33.043,40.747) R13.1@32.734,40.438 ; U3.7@35.118,42.443 U3.7 35.22,40.739 34.79,40.31 ; U3.6 36.52,41.1 35.73,40.31 34.79,40.31
NetR13_2: R13.2 R14.1 U3.9 | length 9.8
  TopLayer w0.4: R13.2 32.77,39.077 35.896,39.077 36.52,38.453 U3.9 R14.1 ; R13.2@32.734,38.785 cw(c33.439,38.08) 33.439,39.077 ; R14.1@36.392,34.443 ccw(c36.083,34.752) 36.52,34.752 ccw(c36.957,34.752) R14.1@36.648,34.443
NetR15_1: R15.1 U1.10 | length 4.6
  TopLayer w0.6: R15.1 17.011,37.085 U1.10 ; R15.1@16.644,36.603 cw(c17.807,35.439) 17.807,37.085
NetR18_2: R18.2 R20.1 U1.6 | length 38.6
  TopLayer w0.4: U1.6@24.81,38.387 v1(26.48,38.387) R20.1@27.474,38.387 ; v1@26.374,38.281 ccw(c26.118,38.025) 26.118,38.387 ccw(c26.118,38.75) v1@26.374,38.493 ; v1@26.586,38.281 cw(c26.843,38.025) 26.843,38.387 cw(c26.843,38.75) v1@26.586,38.493 ; 27.031,38.387 cw(c27.031,37.942) R20.1@27.346,38.257 ; 27.043,38.387 ccw(c27.043,38.816) R20.1@27.346,38.513
  TopLayer w0.6: v1@37.254,13.945 R18.2
  BottomLayer w0.6: v1(26.48,38.387) 28.956,38.387 30.68,36.664 30.68,16.074 32.86,13.894 v1(37.203,13.894)
NetR22_2: R22.2 U1.7 | length 41.1
  TopLayer w0.6: v1(23.224,39.685) U1.7 ; v1(37.203,12.014) R22.2
  BottomLayer w0.6: v1(23.224,39.685) 23.224,35.628 24.376,34.476 27.907,34.476 28.782,33.6 28.782,15.634 32.403,12.014 v1(37.203,12.014)
PH+: J10.1 J10.2 J10.3 R4.1 | length 16
  TopLayer w0.8: R4.1 38.963,47.488 J10.1@41.945,50.47
  TopLayer w1.5: J10.3 J10.1
PH-: C9.2 J3.1 R7.1 | length 9.2
  TopLayer w0.6: C9.2@27.469,46.153 cw(c26.41,45.095) 27.907,45.095 ; C9.2 27.907,45.83 R7.1
  TopLayer w0.762: J3.1 27.526,47.099 C9.2
S0: J2.14 U2.11 | length 36.3
  TopLayer w0.6: v1(35.542,5.461) 36.06,5.979 U2.11
  BottomLayer w0.4: J2.14@14.825,2.955 ccw(c13.963,3.817) 15.181,3.817 ; J2.14@15.181,2.54 15.181,3.886 ; J2.14@15.608,2.998 cw(c16.32,3.886) 15.181,3.886 ; v1@35.436,5.355 ccw(c35.18,5.099) 35.18,5.461 ccw(c35.18,5.823) v1@35.436,5.567 ; v1(35.542,5.461) 16.756,5.461 15.181,3.886
S1: J2.13 U2.10 | length 36.8
  TopLayer w0.4: v1@33.063,4.547 34.79,6.274 U2.10 ; v1@33.114,4.747 ccw(c33.114,5.11) 33.37,4.853 ccw(c33.626,4.597) v1@33.264,4.597
  BottomLayer w0.4: J2.13@15.181,0 16.451,1.27 16.451,3.658 17.34,4.547 33.063,4.547 v1(33.114,4.597) ; J2.13@15.24,0.587 ccw(c15.24,1.864) 16.143,0.961 ; J2.13@15.827,0 cw(c17.387,0) 16.284,1.103
SCK1: J2.12 P4.5 | length 40.1
  TopLayer w0.4: P4.5 -10.541,2.159 -8.306,2.159 -2.498,-3.649 12.67,-3.649 14,-2.319 14,1.24 J2.12 ; J2.12@12.7,1.953 cw(c12.7,0.534) 13.703,1.537 cw(c14.706,2.54) J2.12@13.287,2.54
SGND: C1.2 C2.1 C3.1 C4.2 C5.2 C6.2 C7.2 C8.2 C9.1 C10.1 C13.2 C14.2 C15.1 C16.2 C17.2 C18.2 C19.1 C20.1 C23.1 C24.1 C25.2 C26.1 C42.2 CA1.2 CA2.2 CA3.2 CA4.1 CA5.1 J2.5 J2.6 J3.2 J3.3 P4.2 R6.2 R15.2 R20.2 TP5.1 U2.6 U2.8 U2.9 U10.2 U10.4 U11.2 U11.4 U11_1.2 U12.3 U21.4 U21.12 U21.19 Y1.2 | length 99.8
  TopLayer w0.4: v1(38.905,-5.283) 39.369,-4.819 U21.12 ; v1@38.905,-5.133 ccw(c38.905,-4.771) 39.161,-5.027 ccw(c39.417,-5.283) v1@39.055,-5.283 ; v1(42.619,2.673) U21.4 ; v1@43.813,-4.76 ccw(c43.557,-4.504) 43.919,-4.504 ccw(c44.281,-4.504) v1@44.025,-4.76 ; v1(43.919,-4.866) U21.19
  TopLayer w0.6: v1(14.173,34.806) 14.224,34.857 C4.2@15.189,34.857 ; C23.1 v1@15.707,11.583 ; C3.1@14.834,33.053 14.834,33.638 15.189,33.993 ; C3.1@14.913,33.068 cw(c15.908,33.275) 15.189,33.993 ; R15.2 C4.2@15.189,34.857 ; v1(18.534,44.712) 19.906,44.712 20.033,44.585 C20.1 ; C10.1 v1(26.129,45.163) C9.1@26.129,45.855 ; R20.2 27.474,41.108 v1(27.51,41.144) ; C17.2 28.512,34.349 29.198,35.035 v1(29.198,35.352) ; 28.888,34.725 ccw(c28.261,35.352) v1@29.148,35.352 ; v1(32.394,16.627) U2.9 ; v1(33.52,20.549) U2.8 ; v1@34.638,29.923 R6.2 ; v1@36.06,20.777 U2.6 ; v1(38.6,29.745) C13.2 ; C18.2 v1(42.41,-6.509) ; C2.1 43.62,12.37 v1(43.919,12.071) ; 43.077,12.37 cw(c43.077,11.228) v1@43.884,12.035 ; v1(46.5,7.442) 46.566,7.442 C16.2 ; 15.189,33.993 C4.2@15.189,34.857
  TopLayer w0.762: C25.2 v1(7.682,11.583)
  TopLayer w0.8: CA5.1@4.037,21.726 cw(c3.44,21.129) 4.285,21.129 cw(c5.13,21.129) CA5.1@4.532,21.726 ; v1@4.235,20.308 ccw(c4.884,20.308) 4.425,19.849 ; CA5.1 v1(4.285,20.308) ; v1@4.722,19.483 cw(c5.283,20.308) v1(4.285,20.308) ; v1@4.744,19.474 cw(c4.803,19.989) v1@4.285,19.989 ; C26.1 4.918,19.356 v1(4.75,19.524) v1@4.285,19.989 ; U12.3 9.081,13.999 v1(9.646,14.565) 10.247,15.165 11.268,15.165 ; CA4.1@7.991,8.892 v1(9.185,8.892) ; CA4.1@8.091,8.611 cw(c8.769,7.932) 8.769,8.892 ; CA4.1@8.091,9.106 ccw(c8.608,9.622) 8.608,8.892 ; 11.198,15.165 ccw(c11.198,16.023) U10.2@11.804,15.416 ; 11.208,15.106 cw(c11.826,14.488) U10.2@11.826,15.362 ; U10.2@11.802,15.414 cw(c11.268,15.863) 11.268,15.165 ; C1.2 v1(12.844,30.186) ; C24.1 15.608,19.374 v1(15.914,19.68) 16.22,19.986 16.22,22.036 CA3.2 ; U10.4@14.925,15.394 U10.2 11.496,15.394 11.268,15.165 ; 15.295,19.374 ccw(c15.295,20.298) 15.949,19.645 ccw(c15.295,20.298) v1@16.22,20.298 ; 16.172,19.938 ccw(c15.732,20.379) v1@16.323,20.574 ; 16.22,20.962 cw(c17.255,20.962) CA3.2@16.523,21.694 ; CA2.2 v1(17.639,8.858) ; CA2.2@16.718,8.611 cw(c17.315,8.013) 17.315,8.858 cw(c17.315,9.703) CA2.2@16.718,9.106 ; U11_1.2@20.543,28.202 21.481,27.264 U11.2 21.481,23.087 U11.4 ; U11_1.2@20.887,28.607 ccw(c22.172,28.411) 21.253,27.492 ; U11.4@21.043,24.028 ccw(c19.985,25.086) U11.2@21.481,25.086 ; U11.2@21.481,25.074 ccw(c22.96,25.074) U11.4@21.914,24.028 ; 25.46,23.808 ccw(c25.46,25.169) CA1.2@26.76,24.767 ; 25.627,24.046 ccw(c24.773,24.9) CA1.2@25.98,24.9 ; CA1.2@25.996,25.003 cw(c24.376,25.504) v2(24.376,23.808) 25.388,23.808 CA1.2 ; C42.2@26.481,-5.046 ccw(c27.994,-5.046) 26.924,-6.116 ; C42.2 26.5,-5.692 v1(27.25,-6.442) ; v1(33.393,24.257) C15.1 ; v1(34.409,45.898) C8.2 ; C7.2 v1(42.146,34.315) ; v1(41.827,8.306) C14.2@43.095,8.306 ; C5.2 43.884,25.308 v1(43.919,25.273) ; v1@4.285,19.989 v1(4.285,20.308)
  TopLayer w1: Y1.2@35.188,-8.032 ccw(c34.335,-7.179) 35.542,-7.179 ccw(c36.749,-7.179) Y1.2@35.896,-8.032 ; Y1.2 v2(35.542,-6.538) ; C6.2 49.022,42.037 v1(49.657,41.402)
  other v1: 0.127,7.493 -8.543,10.643 -5.371,10.632 -2.413,10.643 27.5,11.401 15.734,11.611 29.694,13.018 9.25,15.901 29.756,18.308 16.276,20.558 36.06,20.549 38.25,26.701 44.61,27.645 34.638,29.769 44.593,29.808 29.774,30.601 37.5,31.501 44.593,31.808 44.75,34.201 33.699,35.476 48.006,35.941 44.75,36.147 42.5,39.077 48.006,39.37 33.099,43.054 16,44.858 30.294,44.858 33,45.901 29.382,46.023
  other v2: 16.093,-2.692 18.25,-2.699
SSEL1_B: J2.9 P4.6 R26.1 | length 42.3
  TopLayer w0.4: R26.1 P4.6 -11.989,1.067 -8.585,1.067 -2.826,-4.692 v1(9.368,-4.692) ; v1@9.262,-4.798 ccw(c9.006,-5.054) 9.006,-4.692 ccw(c9.006,-4.33) v1@9.262,-4.586
  BottomLayer w0.4: v1(9.368,-4.692) 10.16,-3.9 J2.9 ; v1@9.368,-4.542 ccw(c9.368,-4.18) 9.624,-4.436 ccw(c9.88,-4.692) v1@9.518,-4.692 ; J2.9@9.745,-0.415 cw(c8.742,-1.418) 10.16,-1.418 cw(c11.578,-1.418) J2.9@10.575,-0.415
TEMP: C19.2 J3.4 R19.2 R21.2 | length 16.7
  TopLayer w0.762: J3.4@8.695,50.471 12.887,46.279 R19.2@23.638,46.279
VCC: C18.1 C42.1 J2.19 J2.20 P4.1 R26.2 U21.13 Y1.4 | length 92.3
  TopLayer w0.4: 40.019,-6.003 ccw(c40.555,-6.003) C18.1@40.176,-6.381 ; U21.13 40.019,-6.509 C18.1@40.048,-6.538
  TopLayer w0.6: R26.2 -5.664,9.373 -3.886,7.595 P4.1 ; v1(40.048,-7.692) C18.1@40.048,-6.538
  TopLayer w1.2: v1@25,-3.636 Y1.4
  MidLayer1 w1.2: P4.1@-3.835,5.664 -3.835,-3.607 -0.75,-6.692 21.103,-6.692 22.801,-4.993 ; J2.20@22.801,2.54 22.801,-3.636 ; v1(24.85,-3.649) 22.815,-3.649 22.801,-3.636 ; v1(40.048,-7.692) 38.048,-9.692 27.5,-9.692 22.801,-4.993 ; 22.801,-4.993 22.801,-3.636
XI: U21.11 Y1.3 | length 9.4
  TopLayer w0.4: Y1.3@35.755,-4.267 38.448,-4.267 38.719,-3.996 U21.11 ; Y1.3@35.825,-3.603 ccw(c37.428,-2) 37.428,-4.267 ; Y1.3@36.108,-4.452 cw(c36.553,-4.897) 36.553,-4.267 ; Y1.3@36.108,-3.32 ccw(c38.394,-1.034) 38.394,-4.267
XO: U21.10
Y0: U1.1 U1.2 U2.13 | length 29.2
  TopLayer w0.4: U1.1 26.891,31.885 ; U1.2 26.454,33.185 26.891,32.749 26.891,31.885 ; U2.13 38.6,17.956 37.84,18.717 31.992,18.717 28.821,21.888 28.821,30.743 27.679,31.885 26.891,31.885
Y1: R18.1 R22.1 U2.14 | length 6.1
  TopLayer w0.4: R22.1@39.691,12.142 ccw(c39.26,12.574) 39.87,12.574 ; R18.1@39.691,13.817 cw(c39.26,13.385) 39.87,13.385 ; R18.1@39.691,14.073 ccw(c39.26,14.504) 39.87,14.504 ; R22.1@39.87,12.014 U2.14
pads on no net: P6.2 U2.1 U2.2 U2.4 U2.5 U2.12 U21.5 U21.6 U21.7 U21.16 U21.17 U21.18 Y1.1

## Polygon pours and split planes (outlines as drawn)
SGND on TopLayer "BottomLayer-No Net" (hatched 90Degree grid 0.3 track 0.3, remove dead copper, pour order 14): -17.78,11.887 2.997,11.887 3.099,11.989 3.099,26.086 10.693,33.68 10.693,48.209 10.871,48.387 52.629,48.387 52.629,-11.836 52.807,-12.014 4.267,-12.014 4.267,5.283 4.166,5.385 -17.145,5.385 -17.78,4.75
+5V on TopLayer "TopLayer-+5V" (hatched 90Degree grid 0.3 track 0.3, remove dead copper, pour order 11): 14.265,16.842 13.579,16.156 10.506,16.156 10.506,24.03 14.443,24.03 14.443,20.423 13.681,19.661 13.681,17.934 14.265,17.35
-5V on TopLayer "TopLayer--5V" (hatched 90Degree grid 0.3 track 0.3, pour order 12): 6.75,17.622 6.75,26.701 9.515,26.701 9.515,17.748 9.409,17.622
+5V on MidLayer1 "MidLayer1-+5V" (hatched 90Degree grid 0.3 track 0.3, remove dead copper, pour order 13): 10.5,24.509 14.979,24.509 16,23.488 16.351,23.138 31.25,23.138 38.286,23.138 38.905,23.757 39.71,24.562 39.71,34.73 37.955,36.485 29,36.485 29,38.349 29.564,38.913 29.75,39.099 39.75,39.099 42.842,36.007 42.842,25.933 42.842,21.831 41.319,20.308 11.006,20.308 10.506,20.808
-5V on MidLayer1 "MidLayer1--5V" (hatched 90Degree grid 0.3 track 0.3, remove dead copper, pour order 15): 9.573,20.089 9.573,25.391 9.598,25.416 25.638,25.416 26.519,24.534 26.628,24.425 36.607,24.425 37.233,24.425 37.233,26.978 36.6,27.612 36.304,27.907 23.607,27.907 7.642,27.907 6.142,26.407 6.142,22.415 6.607,21.95 6.607,20.221 6.74,20.089
+2.5V on MidLayer1 "MidLayer1-+2.5V" (hatched 90Degree grid 0.3 track 0.3, remove dead copper, pour order 16): 24.594,28.801 24.594,29.139 23.132,30.601 22.583,31.15 22.583,33.607 22.583,44.712 22.608,44.737 25.137,44.737 25.993,43.882 25.993,33.822 28.161,31.654 28.161,28.98 27.982,28.801
VCC on MidLayer1 "BottomLayer-No Net" (hatched 90Degree grid 0.3 track 0.3, remove dead copper, pour order 18): 21.514,4.293 21.514,-3.937 20.396,-5.055 -0.229,-5.055 -0.432,-5.258 -0.432,-9.169 -0.508,-9.246 22.758,-9.246 25.349,-6.655 25.349,4.216 25.273,4.293
+24V_IN on BottomLayer "BottomLayer-No Net" (hatched 90Degree grid 0.3 track 0.3, remove dead copper, pour order 14): -11.887,-4.445 -10.262,-4.445 -4.242,1.575 -1.676,4.14 1.092,4.14 1.092,1.702 1.118,1.676 -0.965,1.676 -3.886,-1.245 -9.525,-6.883 -11.887,-6.883
-2.5V on BottomLayer "BottomLayer--2.5V" (hatched 90Degree grid 0.3 track 0.3, remove dead copper, pour order 20): 17.893,40.292 28.698,40.292 30.793,38.197 31.406,37.585 33.561,37.585 33.561,40.09 31.093,42.558 29.809,43.842 17.893,43.842
SGND on BottomLayer "BottomLayer-No Net" (hatched 90Degree grid 0.3 track 0.3, remove dead copper, pour order 19): 10.668,48.184 53.467,48.184 53.492,48.209 53.492,-11.455 52.908,-12.04 4.318,-12.04 4.191,-11.913 4.191,4.978 4.394,5.182 -17.729,5.182 -17.856,5.055 -17.856,11.862 -17.729,11.989 3.15,11.989 3.226,11.913 3.226,26.441 10.693,33.909
SGND on GND (split plane): 52.438,-11.619 4.028,-11.619 4.028,4.572 4.021,4.622 4.002,4.668 3.971,4.708 3.931,4.738 3.885,4.758 3.835,4.764 -19.848,4.764 -19.848,12.051 2.667,12.051 2.717,12.057 2.763,12.076 2.803,12.107 2.833,12.147 2.853,12.193 2.859,12.243 2.859,26.692 10.423,34.256 10.453,34.296 10.473,34.342 10.479,34.392 10.479,56.704 52.438,56.704
24VGND on GND (split plane): 1.129,-11.832 -19.813,-11.832 -19.813,3.44 1.129,3.44
no net on GND (split plane): 10.095,34.471 2.531,26.907 2.501,26.868 2.493,26.848 2.481,26.821 2.475,26.772 2.475,12.435 -20.041,12.435 -20.09,12.428 -20.137,12.409 -20.176,12.379 -20.207,12.339 -20.226,12.293 -20.233,12.243 -20.233,4.572 -20.226,4.522 -20.207,4.476 -20.176,4.436 -20.137,4.406 -20.09,4.386 -20.041,4.38 3.643,4.38 3.643,-11.811 3.646,-11.832 1.513,-11.832 1.513,3.632 1.506,3.682 1.487,3.728 1.457,3.768 1.417,3.799 1.371,3.818 1.321,3.824 -20.015,3.824 -20.065,3.818 -20.111,3.799 -20.151,3.768 -20.182,3.728 -20.201,3.682 -20.201,3.681 -20.21,3.659 -20.217,3.607 -20.217,-11.832 -20.956,-11.832 -20.956,13.016 1.778,13.016 1.828,13.022 1.874,13.042 1.914,13.072 1.944,13.112 1.964,13.158 1.97,13.208 1.97,27.302 8.772,34.103 8.802,34.143 8.822,34.189 8.828,34.239 8.828,56.8 10.095,56.8
no net on GND (split plane): -32.577,13.572 -32.58,13.565 -32.587,13.513 -32.587,3.632 -32.58,3.58 -32.577,3.573 -32.577,-11.832 -32.64,-11.832 -32.64,56.8 -32.577,56.8
IAGND on GND (split plane): 8.444,34.319 1.642,27.517 1.612,27.477 1.604,27.458 1.592,27.431 1.586,27.381 1.586,13.4 -21.099,13.4 -21.106,13.403 -21.158,13.41 -21.21,13.403 -21.259,13.383 -21.301,13.351 -21.333,13.309 -21.353,13.26 -21.36,13.208 -21.36,-11.832 -32.193,-11.832 -32.193,3.573 -32.19,3.58 -32.183,3.632 -32.183,4.575 -32.141,4.607 -32.109,4.649 -32.089,4.698 -32.082,4.75 -32.089,4.802 -32.109,4.851 -32.141,4.892 -32.183,4.935 -32.183,13.513 -32.19,13.565 -32.193,13.572 -32.193,56.8 8.444,56.8

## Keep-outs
KeepOutLayer:
  lines w0.254: -31.136,57.108 50.964,57.108
  lines w0.3: -33,-12.192 52.605,-12.192 52.799,-12.192 51,57.161 -31.25,57.161 -33,-12.192

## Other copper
GND (plane layer: these items are gaps in the copper):
  lines w0.381: -32.385,3.632 -32.385,-12.573 1.778,-12.573 1.321,-12.573 1.321,3.632 -20.015,3.632 ; -32.385,13.183 -32.385,57.15 8.636,57.15 ; -21.158,13.208 1.778,13.208 1.778,27.381 8.636,34.239 8.636,57.15 ; 8.636,57.15 8.636,57.277 8.636,57.15 ; 10.287,56.896 10.287,34.392 2.667,26.772 2.667,12.243 -20.041,12.243 -20.041,4.572 3.835,4.572 3.835,-11.811 53.848,-11.811 53.848,56.896 10.287,56.896 ; 10.287,56.896 10.287,57.15 10.287,56.896
  lines w0.4: -32.385,3.632 -32.385,13.513 ; -32.334,4.801 -32.283,4.75 ; -21.158,-12.342 -21.158,13.208 ; -20.041,-12.446 -20.015,-12.421 -20.015,3.607

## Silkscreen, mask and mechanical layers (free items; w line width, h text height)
TopOverlay:
  lines w0.254: -33.731,66.058 -31.191,66.065 ; -32.717,66.569 -31.191,66.065 ; -32.714,65.553 -31.191,66.065 ; -31.191,57.099 -31.191,66.624 ; -31.192,66.319 -31.19,65.811 ; -14.166,66.37 -14.164,65.862 ; -14.165,60.325 -14.165,66.734 ; -12.643,66.629 -14.165,66.116 ; -12.64,65.613 -14.165,66.116 ; -11.625,66.124 -14.165,66.116 ; 16.801,29.859 cw(c20.552,28.551) 24.326,29.788 ; 41.935,66.005 44.475,66.015 ; 42.949,66.517 44.475,66.015 ; 42.953,65.501 44.475,66.015 ; 44.474,66.269 44.476,65.761 ; 44.475,60.63 44.475,66.852 ; 51.002,66.294 51.004,65.786 ; 51.003,57.15 51.003,67.031 ; 52.525,66.554 51.003,66.04 ; 52.529,65.538 51.003,66.04 ; 53.543,66.05 51.003,66.04
  lines w0.3: -30.785,3.15 -2.311,3.15 -2.311,48.362 -30.785,48.362 -30.785,3.175 ; 45.603,31.975 48.335,31.975 ; 45.697,25.444 48.382,25.444
  text "17.026 (mm)" at -30.31,62.411 h1.52 r0.17
  text "6.528 (mm)" at 40.745,62.343 h1.52 r0.22
  text "Glass" at 33.401,55.118 h1.4
  text "Ref" at 22.479,54.991 h1.4
  text "+A(mA)-" at -13.335,54.864 h1.4
  text "-B(mA)+" at -2.921,54.864 h1.4
  text "T+" at 8.001,54.864 h1.4
  text "T-/SG" at 13.081,54.864 h1.4
  text "Sanpell_SIG_V5.2" at -21.488,41.961 h1.5
Mechanical1:
  lines w0.3: -34.544,46.685 0.66,46.685 ; -32.018,5.69 -6.858,5.69 ; -31.175,57.16 50.925,57.16 ; -14.015,2.508 -14.015,44.6

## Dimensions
-21.989,44.6 to -30.805,46.901 on Mechanical1
-14.015,44.6 to -21.99,44.775 on Mechanical1
-32.582,46.665 to -32.018,5.69 on Mechanical1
